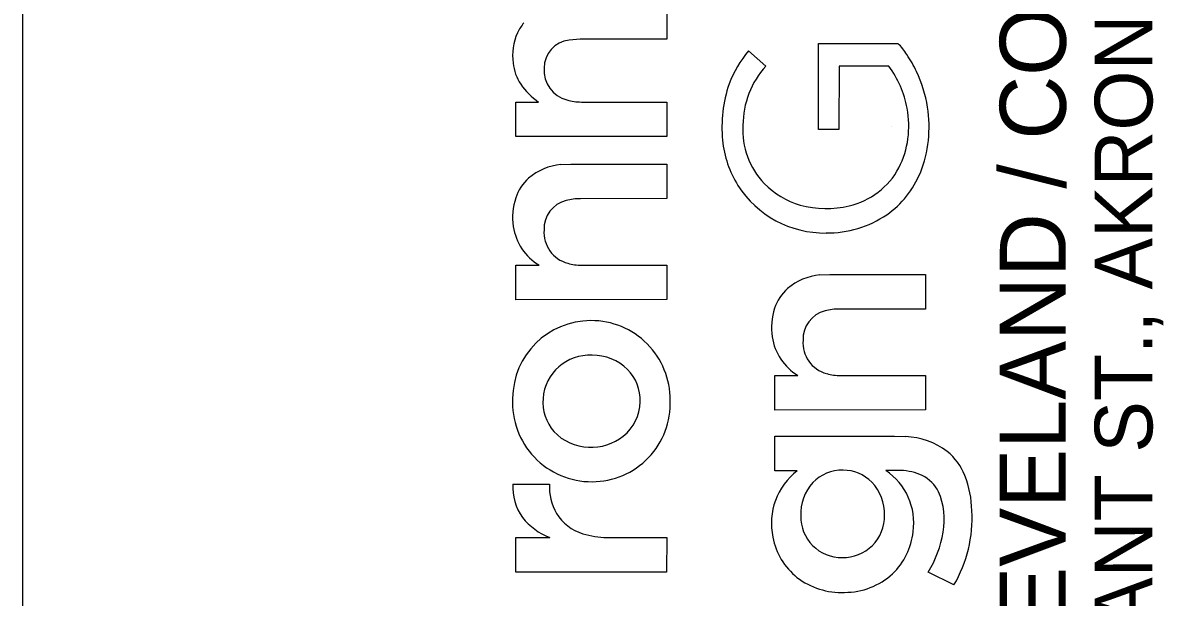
# Model space of a CAD drawing. Extents: x 0 to 34, y 0 to 22.
# Drawn here: x 32 to 32.984, y 3.094 to 3.59 of the extents above; entities that cross this region are included whole.
import ezdxf

# ---------------------------------------------------------------- set-up
doc = ezdxf.new("R2010")
doc.units = 0
doc.layers.add('SH_Border', color=7, linetype='Continuous')
doc.layers.add('SH_Data', color=7, linetype='Continuous')

msp = doc.modelspace()

# ---------------------------------------------------------------- linework, layer by layer
at = {"layer": 'SH_Border'}
msp.add_line((32, 0.5), (32, 21.5), dxfattribs=at)
at = {"layer": 'SH_Data'}
for p, q in [((32.55571, 3.60548), (32.55571, 3.57568)), ((32.4809, 3.57567), (32.47143, 3.57474)), ((32.55571, 3.57568), (32.4809, 3.57567)), ((32.62636, 3.56548), (32.64114, 3.55241)), ((32.6868, 3.57185), (32.75516, 3.57192)), ((32.6868, 3.49778), (32.6868, 3.57185)), ((32.70448, 3.55241), (32.70432, 3.49775)), ((32.74737, 3.55227), (32.70448, 3.55241)), ((32.42542, 3.49152), (32.42545, 3.52138)), ((32.42545, 3.52138), (32.44515, 3.52138)), ((32.48206, 3.52138), (32.55571, 3.52136)), ((32.55571, 3.52136), (32.55571, 3.49156)), ((32.70432, 3.49775), (32.6868, 3.49778)), ((32.75, 3.5), (32.75, 3.5)), ((32.55571, 3.49156), (32.42542, 3.49152)), ((32.46439, 3.46736), (32.47289, 3.46783)), ((32.47289, 3.46783), (32.55571, 3.46783)), ((32.55571, 3.46783), (32.55571, 3.43804)), ((32.55571, 3.43804), (32.4814, 3.43796)), ((32.42542, 3.38066), (32.44552, 3.38071)), ((32.42542, 3.35086), (32.42542, 3.38066)), ((32.48222, 3.38071), (32.55569, 3.38071)), ((32.55569, 3.38071), (32.55571, 3.35096)), ((32.68784, 3.3722), (32.69634, 3.37266)), ((32.69634, 3.37266), (32.77916, 3.37266)), ((32.77916, 3.37266), (32.77917, 3.34287)), ((32.55571, 3.35096), (32.42542, 3.35086)), ((32.77917, 3.34287), (32.70485, 3.3428)), ((32.64888, 3.2855), (32.66897, 3.28555)), ((32.64888, 3.25569), (32.64888, 3.2855)), ((32.70568, 3.28555), (32.77915, 3.28555)), ((32.77915, 3.28555), (32.77917, 3.25579)), ((32.77917, 3.25579), (32.64888, 3.25569)), ((32.6489, 3.20336), (32.64889, 3.23322)), ((32.64889, 3.23322), (32.75236, 3.23322)), ((32.75236, 3.23322), (32.76191, 3.23285)), ((32.66836, 3.20336), (32.6489, 3.20336)), ((32.75763, 3.20356), (32.74487, 3.20361)), ((32.42299, 3.19193), (32.45454, 3.19193)), ((32.42542, 3.14577), (32.45473, 3.14579)), ((32.42542, 3.11593), (32.42542, 3.14577)), ((32.50413, 3.14581), (32.55571, 3.14573)), ((32.55571, 3.14573), (32.55565, 3.11593)), ((32.55565, 3.11593), (32.42542, 3.11593)), ((32.8036, 3.10491), (32.7812, 3.11598))]:
    msp.add_line(p, q, dxfattribs=at)
for points in [[(32.48218, 3.60553), (32.55571, 3.60548), (32.55571, 3.57568), (32.4809, 3.57567), (32.47143, 3.57474)], [(32.62636, 3.56548), (32.64114, 3.55241)], [(32.74737, 3.55227), (32.70448, 3.55241), (32.70432, 3.49775), (32.6868, 3.49778), (32.6868, 3.57185), (32.75516, 3.57192)], [(32.42542, 3.49152), (32.42545, 3.52138), (32.44515, 3.52138)], [(32.48206, 3.52138), (32.55571, 3.52136), (32.55571, 3.49156), (32.42542, 3.49152)], [(32.46439, 3.46736), (32.47289, 3.46783), (32.55571, 3.46783), (32.55571, 3.43804), (32.4814, 3.43796)], [(32.42542, 3.35086), (32.42542, 3.38066), (32.44552, 3.38071)], [(32.48222, 3.38071), (32.55569, 3.38071), (32.55571, 3.35096), (32.42542, 3.35086)], [(32.68784, 3.3722), (32.69634, 3.37266), (32.77916, 3.37266), (32.77917, 3.34287), (32.70485, 3.3428)], [(32.64888, 3.25569), (32.64888, 3.2855), (32.66897, 3.28555)], [(32.70568, 3.28555), (32.77915, 3.28555), (32.77917, 3.25579), (32.64888, 3.25569)], [(32.66836, 3.20336), (32.6489, 3.20336), (32.64889, 3.23322), (32.75236, 3.23322), (32.76191, 3.23285)], [(32.75763, 3.20356), (32.74487, 3.20361)], [(32.42299, 3.19193), (32.45454, 3.19193)], [(32.50413, 3.14581), (32.55571, 3.14573), (32.55565, 3.11593), (32.42542, 3.11593)], [(32.42542, 3.11593), (32.42542, 3.14577), (32.45473, 3.14579)], [(32.8036, 3.10491), (32.7812, 3.11598)]]:
    msp.add_lwpolyline(points, dxfattribs=at)
for centre, radius, start, end in [((32.46194, 3.56452), 0.03875, 139.52447, 154.84698), ((32.46194, 3.56452), 0.03875, 139.52447, 154.84698), ((32.47144, 3.5612), 0.04877, 156.06382, 187.3493), ((32.47144, 3.5612), 0.04877, 156.06382, 187.3493), ((32.47421, 3.55056), 0.02434, 96.5532, 179.94902), ((32.47421, 3.55056), 0.02434, 96.5532, 179.94902), ((32.70163, 3.50187), 0.09855, 139.79476, 159.13696), ((32.70163, 3.50187), 0.09855, 139.79476, 159.13696), ((32.72498, 3.53937), 0.04438, 30.98913, 47.16099), ((32.72498, 3.53937), 0.04438, 30.98913, 47.16099), ((32.46461, 3.55974), 0.04181, 186.5579, 213.38846), ((32.46461, 3.55974), 0.04181, 186.5579, 213.38846), ((32.67091, 3.50018), 0.11106, 25.30315, 33.96179), ((32.67091, 3.50018), 0.11106, 25.30315, 33.96179), ((32.47608, 3.54863), 0.02628, 175.722, 255.78627), ((32.47608, 3.54863), 0.02628, 175.722, 255.78627), ((32.69899, 3.50079), 0.07753, 138.25804, 179.70064), ((32.69899, 3.50079), 0.07753, 138.25804, 179.70064), ((32.67889, 3.50099), 0.08556, 10.07509, 36.83189), ((32.67889, 3.50099), 0.08556, 10.07509, 36.83189), ((32.6704, 3.49987), 0.11166, 8.80339, 25.33484), ((32.6704, 3.49987), 0.11166, 8.80339, 25.33484), ((32.47886, 3.57078), 0.0598, 214.70433, 235.68724), ((32.47886, 3.57078), 0.0598, 214.70433, 235.68724), ((32.7187, 3.49968), 0.11536, 161.14379, 185.62812), ((32.7187, 3.49968), 0.11536, 161.14379, 185.62812), ((32.48195, 3.56518), 0.0438, 253.66719, 270.14979), ((32.48195, 3.56518), 0.0438, 253.66719, 270.14979), ((32.68425, 3.50057), 0.08036, 333.46689, 11.03668), ((32.68425, 3.50057), 0.08036, 333.46689, 11.03668), ((32.67564, 3.49977), 0.10649, 338.28866, 9.28548), ((32.67564, 3.49977), 0.10649, 338.28866, 9.28548), ((32.68811, 3.49732), 0.06676, 176.66577, 223.6912), ((32.68811, 3.49732), 0.06676, 176.66577, 223.6912), ((32.69336, 3.49699), 0.08987, 185.50773, 212.01294), ((32.69336, 3.49699), 0.08987, 185.50773, 212.01294), ((32.46871, 3.41767), 0.04988, 94.97056, 130.22484), ((32.46871, 3.41767), 0.04988, 94.97056, 130.22484), ((32.69868, 3.49547), 0.0652, 282.88151, 331.81475), ((32.69868, 3.49547), 0.0652, 282.88151, 331.81475), ((32.46348, 3.42602), 0.04016, 132.22383, 161.68229), ((32.46348, 3.42602), 0.04016, 132.22383, 161.68229), ((32.69835, 3.49168), 0.08241, 305.03061, 337.67573), ((32.69835, 3.49168), 0.08241, 305.03061, 337.67573), ((32.69211, 3.49748), 0.08908, 212.70222, 270.71399), ((32.69211, 3.49748), 0.08908, 212.70222, 270.71399), ((32.69045, 3.50011), 0.07039, 224.02147, 253.88), ((32.69045, 3.50011), 0.07039, 224.02147, 253.88), ((32.47872, 3.42158), 0.05602, 162.27398, 187.79173), ((32.47872, 3.42158), 0.05602, 162.27398, 187.79173), ((32.47482, 3.41206), 0.02498, 103.68683, 182.21395), ((32.47482, 3.41206), 0.02498, 103.68683, 182.21395), ((32.48108, 3.39196), 0.04601, 89.60515, 105.33026), ((32.48108, 3.39196), 0.04601, 89.60515, 105.33026), ((32.69318, 3.51254), 0.08309, 254.45353, 283.9512), ((32.69318, 3.51254), 0.08309, 254.45353, 283.9512), ((32.69429, 3.49979), 0.09138, 269.3273, 304.19632), ((32.69429, 3.49979), 0.09138, 269.3273, 304.19632), ((32.47027, 3.42141), 0.04763, 188.96462, 238.69865), ((32.47027, 3.42141), 0.04763, 188.96462, 238.69865), ((32.47735, 3.40897), 0.02757, 175.58441, 255.13816), ((32.47735, 3.40897), 0.02757, 175.58441, 255.13816), ((32.48183, 3.42286), 0.04215, 254.08913, 270.52838), ((32.48183, 3.42286), 0.04215, 254.08913, 270.52838), ((32.69216, 3.32251), 0.04988, 94.97056, 130.22484), ((32.69216, 3.32251), 0.04988, 94.97056, 130.22484), ((32.68694, 3.33085), 0.04016, 132.22383, 161.68229), ((32.68694, 3.33085), 0.04016, 132.22383, 161.68229), ((32.70217, 3.32642), 0.05602, 162.27398, 187.79173), ((32.70217, 3.32642), 0.05602, 162.27398, 187.79173), ((32.69828, 3.31689), 0.02498, 103.68683, 182.21395), ((32.69828, 3.31689), 0.02498, 103.68683, 182.21395), ((32.70453, 3.29679), 0.04601, 89.60515, 105.33026), ((32.70453, 3.29679), 0.04601, 89.60515, 105.33026), ((32.49014, 3.26543), 0.0674, 89.84756, 179.64047), ((32.49014, 3.26543), 0.0674, 89.84756, 179.64047), ((32.49057, 3.26474), 0.0681, 359.54009, 90.21138), ((32.49057, 3.26474), 0.0681, 359.54009, 90.21138), ((32.69372, 3.32624), 0.04763, 188.96462, 238.69865), ((32.69372, 3.32624), 0.04763, 188.96462, 238.69865), ((32.7008, 3.31381), 0.02757, 175.58441, 255.13816), ((32.7008, 3.31381), 0.02757, 175.58441, 255.13816), ((32.48923, 3.26263), 0.0404, 87.04809, 175.57259), ((32.48923, 3.26263), 0.0404, 87.04809, 175.57259), ((32.49204, 3.25999), 0.04299, 45.84264, 90.98008), ((32.49204, 3.25999), 0.04299, 45.84264, 90.98008), ((32.49458, 3.26421), 0.03821, 357.88569, 44.15902), ((32.49458, 3.26421), 0.03821, 357.88569, 44.15902), ((32.70529, 3.32769), 0.04215, 254.08913, 270.52838), ((32.70529, 3.32769), 0.04215, 254.08913, 270.52838), ((32.49083, 3.26209), 0.06819, 176.8344, 270.40384), ((32.49083, 3.26209), 0.06819, 176.8344, 270.40384), ((32.48729, 3.2625), 0.03848, 175.15378, 221.14706), ((32.48729, 3.2625), 0.03848, 175.15378, 221.14706), ((32.49123, 3.26139), 0.06749, 270.06243, 2.37759), ((32.49123, 3.26139), 0.06749, 270.06243, 2.37759), ((32.49446, 3.26318), 0.0383, 308.28936, 359.43468), ((32.49446, 3.26318), 0.0383, 308.28936, 359.43468), ((32.48919, 3.26607), 0.04228, 223.09994, 268.80895), ((32.48919, 3.26607), 0.04228, 223.09994, 268.80895), ((32.49096, 3.2679), 0.04418, 266.56515, 308.06078), ((32.49096, 3.2679), 0.04418, 266.56515, 308.06078), ((32.75907, 3.16789), 0.06503, 53.40344, 87.49062), ((32.75907, 3.16789), 0.06503, 53.40344, 87.49062), ((32.76517, 3.18039), 0.05141, 21.60748, 50.5577), ((32.76517, 3.18039), 0.05141, 21.60748, 50.5577), ((32.70292, 3.15813), 0.05692, 127.37482, 192.22468), ((32.70292, 3.15813), 0.05692, 127.37482, 192.22468), ((32.70693, 3.16927), 0.0346, 88.47302, 136.42562), ((32.70693, 3.16927), 0.0346, 88.47302, 136.42562), ((32.70814, 3.16963), 0.03424, 44.27195, 90.47623), ((32.70814, 3.16963), 0.03424, 44.27195, 90.47623), ((32.71421, 3.15829), 0.05472, 352.1125, 55.92295), ((32.71421, 3.15829), 0.05472, 352.1125, 55.92295), ((32.75666, 3.15725), 0.04633, 65.01687, 88.8011), ((32.75666, 3.15725), 0.04633, 65.01687, 88.8011), ((32.7626, 3.17155), 0.03085, 26.26808, 63.80301), ((32.7626, 3.17155), 0.03085, 26.26808, 63.80301), ((32.73069, 3.16714), 0.08835, 1.15143, 21.3627), ((32.73069, 3.16714), 0.08835, 1.15143, 21.3627), ((32.46616, 3.18882), 0.04329, 175.87313, 216.34747), ((32.46616, 3.18882), 0.04329, 175.87313, 216.34747), ((32.50087, 3.18948), 0.04639, 176.9688, 209.60636), ((32.50087, 3.18948), 0.04639, 176.9688, 209.60636), ((32.71141, 3.16602), 0.0401, 137.46739, 182.33237), ((32.71141, 3.16602), 0.0401, 137.46739, 182.33237), ((32.70368, 3.166), 0.03996, 358.57141, 43.53765), ((32.70368, 3.166), 0.03996, 358.57141, 43.53765), ((32.73565, 3.16154), 0.05953, 349.30734, 23.43071), ((32.73565, 3.16154), 0.05953, 349.30734, 23.43071), ((32.47466, 3.19716), 0.05511, 218.09809, 248.7907), ((32.47466, 3.19716), 0.05511, 218.09809, 248.7907), ((32.49514, 3.18814), 0.04079, 211.94466, 253.2028), ((32.49514, 3.18814), 0.04079, 211.94466, 253.2028), ((32.70645, 3.1637), 0.03511, 178.88208, 271.08374), ((32.70645, 3.1637), 0.03511, 178.88208, 271.08374), ((32.70818, 3.16404), 0.03546, 268.27882, 1.55016), ((32.70818, 3.16404), 0.03546, 268.27882, 1.55016), ((32.70538, 3.16244), 0.11383, 329.6388, 3.25998), ((32.70538, 3.16244), 0.11383, 329.6388, 3.25998), ((32.70988, 3.15708), 0.05887, 313.74196, 353.8554), ((32.70988, 3.15708), 0.05887, 313.74196, 353.8554), ((32.70738, 3.16334), 0.08771, 327.31495, 351.57478), ((32.70738, 3.16334), 0.08771, 327.31495, 351.57478), ((32.50465, 3.2165), 0.07069, 252.46555, 269.57296), ((32.50465, 3.2165), 0.07069, 252.46555, 269.57296), ((32.70463, 3.15696), 0.05837, 190.75182, 231.28919), ((32.70463, 3.15696), 0.05837, 190.75182, 231.28919), ((32.70632, 3.16112), 0.06269, 232.46061, 272.59022), ((32.70632, 3.16112), 0.06269, 232.46061, 272.59022), ((32.70954, 3.15901), 0.06051, 269.6361, 312.70877), ((32.70954, 3.15901), 0.06051, 269.6361, 312.70877)]:
    msp.add_arc(centre, radius, start, end, dxfattribs=at)

# ---------------------------------------------------------------- texts
for s, height, p in [('450 GRANT ST., AKRON, OH  44311', 0.0498462, (32.97489, 2.83738)), ('AKRON / CLEVELAND / COLUMBUS', 0.056969, (32.90012, 2.638))]:
    msp.add_text(s, height=height, rotation=90, dxfattribs=at).set_placement(p)

doc.saveas('drawing.dxf')
